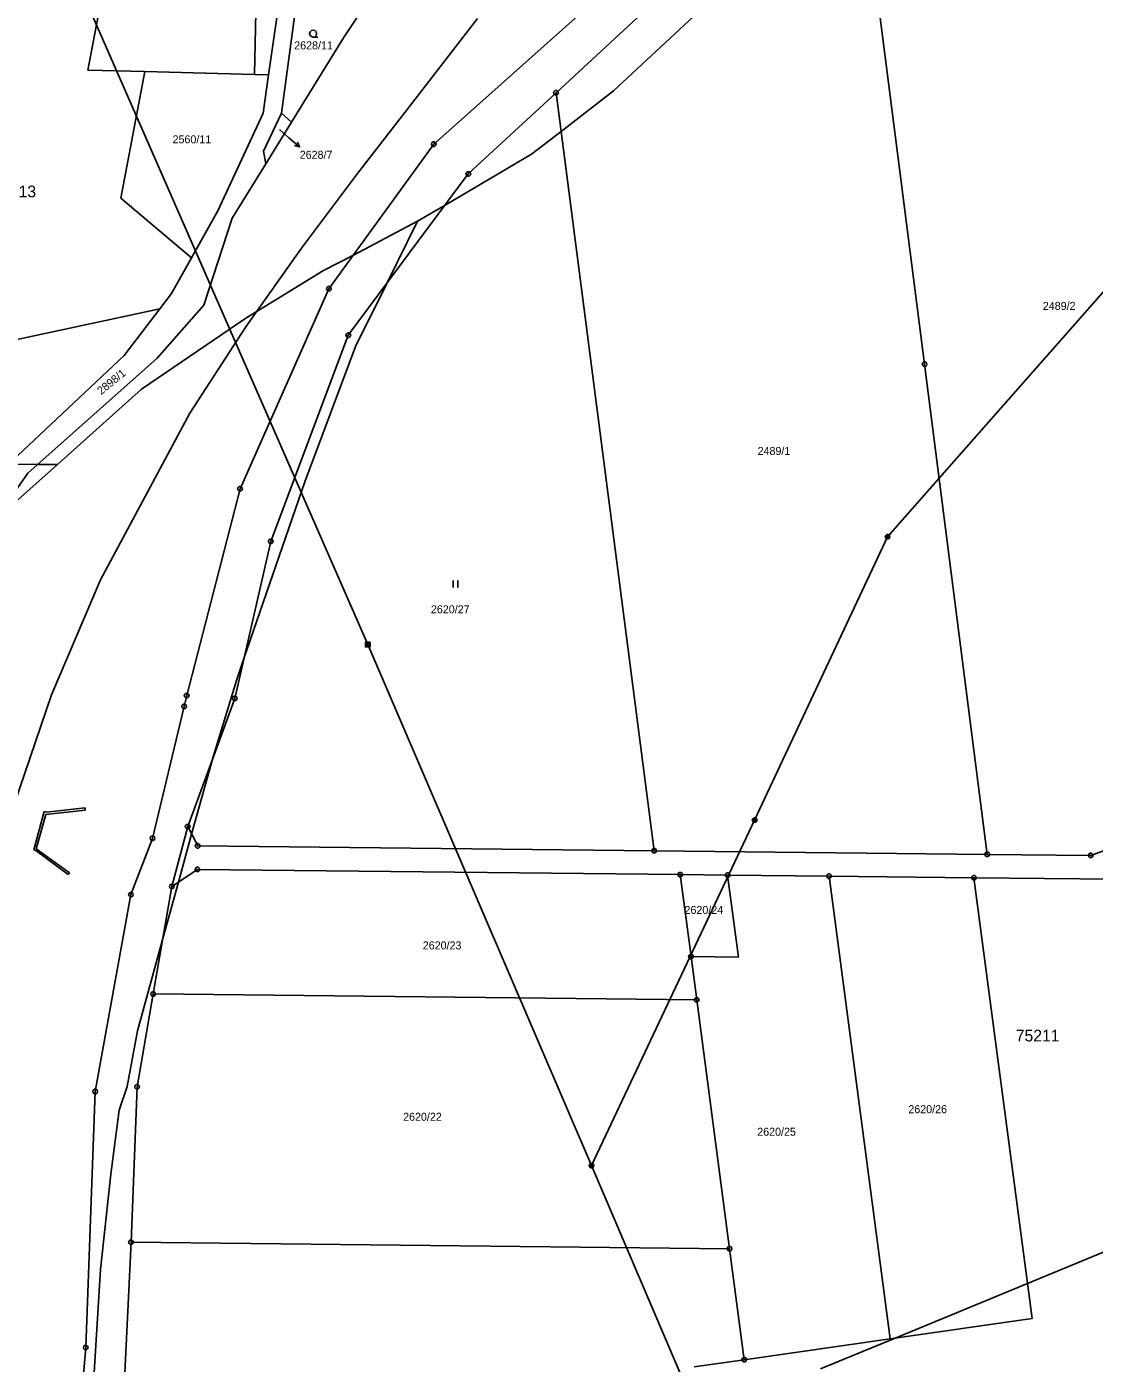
# Model space of a CAD drawing. Extents: x -760611 to -758411, y -1176479 to -1174807.
# Drawn here: x -759476.2 to -759249.4, y -1175576.9 to -1175293 of the extents above; entities that cross this region are included whole.
import ezdxf

# ---------------------------------------------------------------- set-up
doc = ezdxf.new("R2010")
doc.units = 0
for name, color, linetype in [('1', 7, 'Continuous'), ('11', 7, 'Continuous'), ('2', 7, 'Continuous'), ('3', 7, 'Continuous'), ('4', 7, 'Continuous'), ('6', 7, 'Continuous'), ('7', 7, 'Continuous'), ('8', 7, 'Continuous')]:
    doc.layers.add(name, color=color, linetype=linetype)

msp = doc.modelspace()

# ---------------------------------------------------------------- linework, layer by layer
at = {"layer": '1'}
for p, q in [((-759298.74, -1175260.61), (-759285.43, -1175364.72)), ((-759463.25, -1175302.25), (-759458.35, -1175276.62)), ((-759347.43, -1175280.29), (-759389.73, -1175317.99)), ((-759422.12, -1175311.42), (-759418.19, -1175282.22)), ((-759427.83, -1175303.15), (-759427.43, -1175284.24)), ((-759339.76, -1175284.87), (-759363.75, -1175307.07)), ((-759424.83, -1175303.24), (-759422.71, -1175288.64)), ((-759403.18, -1175286.77), (-759408.89, -1175295.4)), ((-759419.93, -1175313.27), (-759408.89, -1175295.4)), ((-759451.11, -1175302.56), (-759463.25, -1175302.25)), ((-759451.11, -1175302.56), (-759456.26, -1175329.44)), ((-759427.83, -1175303.15), (-759451.11, -1175302.56)), ((-759427.83, -1175303.15), (-759424.83, -1175303.24)), ((-759426, -1175311.4), (-759424.83, -1175303.24)), ((-759363.75, -1175307.07), (-759382.39, -1175324.31)), ((-759363.75, -1175307.07), (-759342.89, -1175468.06)), ((-759435.63, -1175332.11), (-759426, -1175311.4)), ((-759422.12, -1175311.42), (-759425.89, -1175319.48)), ((-759419.93, -1175313.27), (-759422.12, -1175311.42)), ((-759419.93, -1175313.27), (-759425.41, -1175322.14)), ((-759425.89, -1175319.48), (-759425.41, -1175322.14)), ((-759389.73, -1175317.99), (-759412.01, -1175348.67)), ((-759432.55, -1175333.69), (-759425.41, -1175322.14)), ((-759382.39, -1175324.31), (-759407.89, -1175358.56)), ((-759456.26, -1175329.44), (-759441.23, -1175342.14)), ((-759441.23, -1175342.14), (-759435.63, -1175332.11)), ((-759438.6, -1175352.18), (-759432.55, -1175333.69)), ((-759445.44, -1175349.68), (-759441.23, -1175342.14)), ((-759412.01, -1175348.67), (-759430.9, -1175391.19)), ((-759447.94, -1175352.94), (-759445.44, -1175349.68)), ((-759447.94, -1175352.94), (-759567.99, -1175378.71)), ((-759455.51, -1175362.85), (-759447.94, -1175352.94)), ((-759448.52, -1175363.4), (-759438.6, -1175352.18)), ((-759407.89, -1175358.56), (-759424.37, -1175402.34)), ((-759479.36, -1175385.29), (-759455.51, -1175362.85)), ((-759475.96, -1175387.88), (-759448.52, -1175363.4)), ((-759272.12, -1175468.82), (-759285.43, -1175364.72)), ((-759482.98, -1175397.79), (-759475.96, -1175387.88)), ((-759430.9, -1175391.19), (-759442.24, -1175435.11)), ((-759424.37, -1175402.34), (-759432, -1175435.71)), ((-759442.24, -1175435.11), (-759442.77, -1175437.4)), ((-759432, -1175435.71), (-759442.02, -1175462.93)), ((-759442.77, -1175437.4), (-759449.49, -1175465.42)), ((-759449.49, -1175465.42), (-759454.08, -1175477.37)), ((-759442.02, -1175462.93), (-759445.38, -1175475.63)), ((-759439.9, -1175467.02), (-759442.02, -1175462.93)), ((-759439.9, -1175467.02), (-759342.89, -1175468.06)), ((-759342.89, -1175468.06), (-759272.12, -1175468.82)), ((-759243.97, -1175466.82), (-759250.12, -1175469.05)), ((-759272.12, -1175468.82), (-759250.12, -1175469.05)), ((-759439.95, -1175472.02), (-759445.38, -1175475.63)), ((-759337.38, -1175473.12), (-759439.95, -1175472.02)), ((-759335.07, -1175490.55), (-759337.38, -1175473.12)), ((-759337.38, -1175473.12), (-759327.28, -1175473.23)), ((-759327.28, -1175473.23), (-759324.97, -1175490.65)), ((-759305.73, -1175473.46), (-759327.28, -1175473.23)), ((-759305.73, -1175473.46), (-759292.73, -1175571.71)), ((-759274.94, -1175473.79), (-759305.73, -1175473.46)), ((-759274.94, -1175473.79), (-759244.94, -1175474.11)), ((-759262.56, -1175567.39), (-759274.94, -1175473.79)), ((-759445.38, -1175475.63), (-759449.35, -1175498.48)), ((-759454.08, -1175477.37), (-759461.69, -1175519.2)), ((-759333.86, -1175499.72), (-759335.07, -1175490.55)), ((-759324.97, -1175490.65), (-759335.07, -1175490.55)), ((-759449.35, -1175498.48), (-759452.78, -1175518.19)), ((-759449.35, -1175498.48), (-759333.86, -1175499.72)), ((-759326.87, -1175552.58), (-759333.86, -1175499.72)), ((-759461.69, -1175519.2), (-759463.68, -1175573.58)), ((-759452.78, -1175518.19), (-759454.06, -1175551.22)), ((-759457.17, -1175615.9), (-759454.06, -1175551.22)), ((-759326.87, -1175552.58), (-759454.06, -1175551.22)), ((-759323.75, -1175576.16), (-759326.87, -1175552.58)), ((-759292.73, -1175571.71), (-759262.56, -1175567.39)), ((-759323.75, -1175576.16), (-759292.73, -1175571.71)), ((-759463.68, -1175573.58), (-759467.05, -1175613.8)), ((-759334.43, -1175577.69), (-759323.75, -1175576.16))]:
    msp.add_line(p, q, dxfattribs=at)
at = {"layer": '11'}
for points in [[(-759393.16, -1175334.36), (-759387.3, -1175330.9), (-759368.94, -1175320.09), (-759362.69, -1175315.26), (-759351.51, -1175306.64), (-759322.58, -1175279.7), (-759303.02, -1175265.41), (-759302.17, -1175262.03)], [(-759469.67, -1175386.02), (-759451.81, -1175370.03), (-759429.7, -1175354.91), (-759413.13, -1175344.84), (-759406.82, -1175341.53), (-759393.16, -1175334.36)], [(-759393.16, -1175334.36), (-759399.81, -1175347.71), (-759406.4, -1175360.95), (-759417.11, -1175389.67)], [(-759479.79, -1175385.97), (-759473.85, -1175386), (-759469.67, -1175386.02)], [(-759478.18, -1175393.6), (-759469.67, -1175386.02)], [(-759417.11, -1175389.67), (-759430.06, -1175427.22), (-759431.68, -1175431.91), (-759436.83, -1175448.81), (-759436.84, -1175448.85), (-759441.18, -1175464.55), (-759443.99, -1175474.7), (-759447.3, -1175486.67), (-759452.72, -1175506.28), (-759454.89, -1175518.12), (-759456.6, -1175523.19), (-759458.34, -1175536.72), (-759460.54, -1175557.02), (-759462.34, -1175585.79), (-759461.62, -1175621.33), (-759460.4, -1175636.57), (-759460.44, -1175646.73), (-759456.01, -1175714.03)], [(-759307.54, -1175578.1), (-759291.72, -1175571.57), (-759263.55, -1175559.94), (-759222.29, -1175542.91)]]:
    msp.add_lwpolyline(points, dxfattribs=at)
at = {"layer": '3'}
for p, q in [((-759385.64, -1175410.66), (-759385.64, -1175412.16)), ((-759384.64, -1175412.16), (-759384.64, -1175410.66))]:
    msp.add_line(p, q, dxfattribs=at)
msp.add_lwpolyline([(-759415.36, -1175295.24), (-759415.74, -1175295.14), (-759416.01, -1175294.87), (-759416.11, -1175294.5), (-759416.01, -1175294.13), (-759415.74, -1175293.86), (-759415.37, -1175293.76), (-759415, -1175293.86), (-759414.73, -1175294.13), (-759414.63, -1175294.51), (-759414.73, -1175294.89), (-759415, -1175295.16), (-759415.38, -1175295.26), (-759414.38, -1175295.26)], dxfattribs=at)
at = {"layer": '4'}
for p, q in [((-759474.71, -1175467.87), (-759472.51, -1175459.72)), ((-759472.51, -1175459.72), (-759472.03, -1175459.85)), ((-759463.78, -1175459.43), (-759472.17, -1175460.33)), ((-759472.03, -1175459.85), (-759463.83, -1175458.93)), ((-759463.83, -1175458.93), (-759463.78, -1175459.43)), ((-759472.17, -1175460.33), (-759474.19, -1175467.62)), ((-759474.3, -1175468), (-759474.71, -1175467.87)), ((-759467.44, -1175473.12), (-759474.3, -1175468)), ((-759474.19, -1175467.62), (-759467.15, -1175472.72)), ((-759467.15, -1175472.72), (-759467.44, -1175473.12))]:
    msp.add_line(p, q, dxfattribs=at)
at = {"layer": '6'}
for p, q in [((-759403.75, -1175424.27), (-759478.28, -1175254.17)), ((-759380.41, -1175291.31), (-759393.68, -1175308.39)), ((-759393.68, -1175308.39), (-759405.91, -1175324.2)), ((-759220.08, -1175318.2), (-759293.3, -1175401.37)), ((-759405.91, -1175324.2), (-759417.82, -1175340.04)), ((-759417.82, -1175340.04), (-759429.67, -1175356.76)), ((-759429.67, -1175356.76), (-759441.55, -1175375.13)), ((-759441.55, -1175375.13), (-759460.56, -1175410.52)), ((-759293.3, -1175401.37), (-759321.55, -1175461.54)), ((-759460.56, -1175410.52), (-759470.94, -1175434.97)), ((-759356.23, -1175534.93), (-759403.75, -1175424.27)), ((-759470.94, -1175434.97), (-759478.91, -1175458.25)), ((-759321.55, -1175461.54), (-759356.23, -1175534.93)), ((-759356.23, -1175534.93), (-759318.62, -1175622.68))]:
    msp.add_line(p, q, dxfattribs=at)
for points in [[(-759293.45, -1175400.89), (-759293.14, -1175400.89), (-759292.89, -1175401.07), (-759292.79, -1175401.36), (-759292.89, -1175401.65), (-759293.14, -1175401.83), (-759293.45, -1175401.83), (-759293.7, -1175401.65), (-759293.8, -1175401.36), (-759293.7, -1175401.07), (-759293.45, -1175400.89), (-759293.42, -1175400.93), (-759293.18, -1175400.93), (-759293.02, -1175401.01), (-759293.58, -1175401.01), (-759293.66, -1175401.09), (-759292.94, -1175401.09), (-759292.94, -1175401.17), (-759293.66, -1175401.17), (-759293.7, -1175401.25), (-759292.9, -1175401.25), (-759292.86, -1175401.33), (-759293.74, -1175401.33), (-759293.74, -1175401.41), (-759292.86, -1175401.41), (-759292.89, -1175401.49), (-759293.7, -1175401.49), (-759293.69, -1175401.57), (-759292.88, -1175401.57), (-759292.93, -1175401.65), (-759293.65, -1175401.65), (-759293.57, -1175401.73), (-759293.01, -1175401.73), (-759293.12, -1175401.81), (-759293.46, -1175401.81)], [(-759404.25, -1175423.77), (-759403.25, -1175423.77), (-759403.25, -1175424.77), (-759404.25, -1175424.77), (-759404.25, -1175423.77), (-759404.19, -1175423.83), (-759403.31, -1175423.83), (-759403.31, -1175423.91), (-759404.19, -1175423.91), (-759404.19, -1175423.99), (-759403.31, -1175423.99), (-759403.31, -1175424.07), (-759404.19, -1175424.07), (-759404.19, -1175424.15), (-759403.31, -1175424.15), (-759403.31, -1175424.23), (-759404.19, -1175424.23), (-759404.19, -1175424.31), (-759403.31, -1175424.31), (-759403.31, -1175424.39), (-759404.19, -1175424.39), (-759404.19, -1175424.47), (-759403.31, -1175424.47), (-759403.31, -1175424.55), (-759404.19, -1175424.55), (-759404.19, -1175424.63), (-759403.31, -1175424.63), (-759403.31, -1175424.71), (-759404.19, -1175424.71)], [(-759321.7, -1175461.06), (-759321.39, -1175461.06), (-759321.14, -1175461.24), (-759321.04, -1175461.53), (-759321.14, -1175461.82), (-759321.39, -1175462), (-759321.7, -1175462), (-759321.95, -1175461.82), (-759322.05, -1175461.53), (-759321.95, -1175461.24), (-759321.7, -1175461.06), (-759321.67, -1175461.1), (-759321.43, -1175461.1), (-759321.27, -1175461.18), (-759321.83, -1175461.18), (-759321.91, -1175461.26), (-759321.19, -1175461.26), (-759321.19, -1175461.34), (-759321.91, -1175461.34), (-759321.95, -1175461.42), (-759321.15, -1175461.42), (-759321.11, -1175461.5), (-759321.99, -1175461.5), (-759321.99, -1175461.58), (-759321.11, -1175461.58), (-759321.14, -1175461.66), (-759321.95, -1175461.66), (-759321.94, -1175461.74), (-759321.13, -1175461.74), (-759321.18, -1175461.82), (-759321.9, -1175461.82), (-759321.82, -1175461.9), (-759321.26, -1175461.9), (-759321.37, -1175461.98), (-759321.71, -1175461.98)], [(-759356.38, -1175534.45), (-759356.07, -1175534.45), (-759355.82, -1175534.63), (-759355.72, -1175534.92), (-759355.82, -1175535.21), (-759356.07, -1175535.39), (-759356.38, -1175535.39), (-759356.63, -1175535.21), (-759356.73, -1175534.92), (-759356.63, -1175534.63), (-759356.38, -1175534.45), (-759356.35, -1175534.49), (-759356.11, -1175534.49), (-759355.95, -1175534.57), (-759356.51, -1175534.57), (-759356.59, -1175534.65), (-759355.87, -1175534.65), (-759355.87, -1175534.73), (-759356.59, -1175534.73), (-759356.63, -1175534.81), (-759355.83, -1175534.81), (-759355.79, -1175534.89), (-759356.67, -1175534.89), (-759356.67, -1175534.97), (-759355.79, -1175534.97), (-759355.82, -1175535.05), (-759356.63, -1175535.05), (-759356.62, -1175535.13), (-759355.81, -1175535.13), (-759355.86, -1175535.21), (-759356.58, -1175535.21), (-759356.5, -1175535.29), (-759355.94, -1175535.29), (-759356.05, -1175535.37), (-759356.39, -1175535.37)]]:
    msp.add_lwpolyline(points, dxfattribs=at)
at = {"layer": '7'}
for p in [(-759422.44, -1175314.95), (-759418.26, -1175318.56)]:
    msp.add_line(p, (-759420.53, -1175316.6), dxfattribs=at)
msp.add_lwpolyline([(-759418.69, -1175317.53), (-759418.26, -1175318.56), (-759419.34, -1175318.29)], dxfattribs=at)
at = {"layer": '8'}
for p, q in [((-759363.87, -1175307.07), (-759363.63, -1175307.07)), ((-759389.85, -1175317.99), (-759389.61, -1175317.99)), ((-759382.51, -1175324.31), (-759382.27, -1175324.31)), ((-759412.13, -1175348.67), (-759411.89, -1175348.67)), ((-759408.01, -1175358.56), (-759407.77, -1175358.56)), ((-759285.55, -1175364.72), (-759285.31, -1175364.72)), ((-759431.02, -1175391.19), (-759430.78, -1175391.19)), ((-759424.49, -1175402.34), (-759424.25, -1175402.34)), ((-759442.36, -1175435.11), (-759442.12, -1175435.11)), ((-759432.12, -1175435.71), (-759431.88, -1175435.71)), ((-759442.89, -1175437.4), (-759442.65, -1175437.4)), ((-759449.61, -1175465.42), (-759449.37, -1175465.42)), ((-759442.14, -1175462.93), (-759441.9, -1175462.93)), ((-759440.02, -1175467.02), (-759439.78, -1175467.02)), ((-759343.01, -1175468.06), (-759342.77, -1175468.06)), ((-759272.24, -1175468.82), (-759272, -1175468.82)), ((-759250.24, -1175469.05), (-759250, -1175469.05)), ((-759440.07, -1175472.02), (-759439.83, -1175472.02)), ((-759337.5, -1175473.12), (-759337.26, -1175473.12)), ((-759327.4, -1175473.23), (-759327.16, -1175473.23)), ((-759305.85, -1175473.46), (-759305.61, -1175473.46)), ((-759275.06, -1175473.79), (-759274.82, -1175473.79)), ((-759445.5, -1175475.63), (-759445.26, -1175475.63)), ((-759454.2, -1175477.37), (-759453.96, -1175477.37)), ((-759335.19, -1175490.55), (-759334.95, -1175490.55)), ((-759449.47, -1175498.48), (-759449.23, -1175498.48)), ((-759333.98, -1175499.72), (-759333.74, -1175499.72)), ((-759461.81, -1175519.2), (-759461.57, -1175519.2)), ((-759452.9, -1175518.19), (-759452.66, -1175518.19)), ((-759454.18, -1175551.22), (-759453.94, -1175551.22)), ((-759326.99, -1175552.58), (-759326.75, -1175552.58)), ((-759463.8, -1175573.58), (-759463.56, -1175573.58)), ((-759323.87, -1175576.16), (-759323.63, -1175576.16))]:
    msp.add_line(p, q, dxfattribs=at)
for points in [[(-759363.6, -1175306.59), (-759363.35, -1175306.77), (-759363.25, -1175307.06), (-759363.35, -1175307.35), (-759363.6, -1175307.53), (-759363.91, -1175307.53), (-759364.16, -1175307.35), (-759364.26, -1175307.06), (-759364.16, -1175306.77), (-759363.91, -1175306.59)], [(-759389.58, -1175317.51), (-759389.33, -1175317.69), (-759389.23, -1175317.98), (-759389.33, -1175318.27), (-759389.58, -1175318.45), (-759389.89, -1175318.45), (-759390.14, -1175318.27), (-759390.24, -1175317.98), (-759390.14, -1175317.69), (-759389.89, -1175317.51)], [(-759382.24, -1175323.83), (-759381.99, -1175324.01), (-759381.89, -1175324.3), (-759381.99, -1175324.59), (-759382.24, -1175324.77), (-759382.55, -1175324.77), (-759382.8, -1175324.59), (-759382.9, -1175324.3), (-759382.8, -1175324.01), (-759382.55, -1175323.83)], [(-759411.86, -1175348.19), (-759411.61, -1175348.37), (-759411.51, -1175348.66), (-759411.61, -1175348.95), (-759411.86, -1175349.13), (-759412.17, -1175349.13), (-759412.42, -1175348.95), (-759412.52, -1175348.66), (-759412.42, -1175348.37), (-759412.17, -1175348.19)], [(-759407.74, -1175358.08), (-759407.49, -1175358.26), (-759407.39, -1175358.55), (-759407.49, -1175358.84), (-759407.74, -1175359.02), (-759408.05, -1175359.02), (-759408.3, -1175358.84), (-759408.4, -1175358.55), (-759408.3, -1175358.26), (-759408.05, -1175358.08)], [(-759285.28, -1175364.24), (-759285.03, -1175364.42), (-759284.93, -1175364.71), (-759285.03, -1175365), (-759285.28, -1175365.18), (-759285.59, -1175365.18), (-759285.84, -1175365), (-759285.94, -1175364.71), (-759285.84, -1175364.42), (-759285.59, -1175364.24)], [(-759430.75, -1175390.71), (-759430.5, -1175390.89), (-759430.4, -1175391.18), (-759430.5, -1175391.47), (-759430.75, -1175391.65), (-759431.06, -1175391.65), (-759431.31, -1175391.47), (-759431.41, -1175391.18), (-759431.31, -1175390.89), (-759431.06, -1175390.71)], [(-759424.22, -1175401.86), (-759423.97, -1175402.04), (-759423.87, -1175402.33), (-759423.97, -1175402.62), (-759424.22, -1175402.8), (-759424.53, -1175402.8), (-759424.78, -1175402.62), (-759424.88, -1175402.33), (-759424.78, -1175402.04), (-759424.53, -1175401.86)], [(-759442.62, -1175436.92), (-759442.37, -1175437.1), (-759442.27, -1175437.39), (-759442.37, -1175437.68), (-759442.62, -1175437.86), (-759442.93, -1175437.86), (-759443.18, -1175437.68), (-759443.28, -1175437.39), (-759443.18, -1175437.1), (-759442.93, -1175436.92)], [(-759442.09, -1175434.63), (-759441.84, -1175434.81), (-759441.74, -1175435.1), (-759441.84, -1175435.39), (-759442.09, -1175435.57), (-759442.4, -1175435.57), (-759442.65, -1175435.39), (-759442.75, -1175435.1), (-759442.65, -1175434.81), (-759442.4, -1175434.63)], [(-759431.85, -1175435.23), (-759431.6, -1175435.41), (-759431.5, -1175435.7), (-759431.6, -1175435.99), (-759431.85, -1175436.17), (-759432.16, -1175436.17), (-759432.41, -1175435.99), (-759432.51, -1175435.7), (-759432.41, -1175435.41), (-759432.16, -1175435.23)], [(-759441.87, -1175462.45), (-759441.62, -1175462.63), (-759441.52, -1175462.92), (-759441.62, -1175463.21), (-759441.87, -1175463.39), (-759442.18, -1175463.39), (-759442.43, -1175463.21), (-759442.53, -1175462.92), (-759442.43, -1175462.63), (-759442.18, -1175462.45)], [(-759449.34, -1175464.94), (-759449.09, -1175465.12), (-759448.99, -1175465.41), (-759449.09, -1175465.7), (-759449.34, -1175465.88), (-759449.65, -1175465.88), (-759449.9, -1175465.7), (-759450, -1175465.41), (-759449.9, -1175465.12), (-759449.65, -1175464.94)], [(-759439.75, -1175466.54), (-759439.5, -1175466.72), (-759439.4, -1175467.01), (-759439.5, -1175467.3), (-759439.75, -1175467.48), (-759440.06, -1175467.48), (-759440.31, -1175467.3), (-759440.41, -1175467.01), (-759440.31, -1175466.72), (-759440.06, -1175466.54)], [(-759342.74, -1175467.58), (-759342.49, -1175467.76), (-759342.39, -1175468.05), (-759342.49, -1175468.34), (-759342.74, -1175468.52), (-759343.05, -1175468.52), (-759343.3, -1175468.34), (-759343.4, -1175468.05), (-759343.3, -1175467.76), (-759343.05, -1175467.58)], [(-759271.97, -1175468.34), (-759271.72, -1175468.52), (-759271.62, -1175468.81), (-759271.72, -1175469.1), (-759271.97, -1175469.28), (-759272.28, -1175469.28), (-759272.53, -1175469.1), (-759272.63, -1175468.81), (-759272.53, -1175468.52), (-759272.28, -1175468.34)], [(-759249.97, -1175468.57), (-759249.72, -1175468.75), (-759249.62, -1175469.04), (-759249.72, -1175469.33), (-759249.97, -1175469.51), (-759250.28, -1175469.51), (-759250.53, -1175469.33), (-759250.63, -1175469.04), (-759250.53, -1175468.75), (-759250.28, -1175468.57)], [(-759439.8, -1175471.54), (-759439.55, -1175471.72), (-759439.45, -1175472.01), (-759439.55, -1175472.3), (-759439.8, -1175472.48), (-759440.11, -1175472.48), (-759440.36, -1175472.3), (-759440.46, -1175472.01), (-759440.36, -1175471.72), (-759440.11, -1175471.54)], [(-759337.23, -1175472.64), (-759336.98, -1175472.82), (-759336.88, -1175473.11), (-759336.98, -1175473.4), (-759337.23, -1175473.58), (-759337.54, -1175473.58), (-759337.79, -1175473.4), (-759337.89, -1175473.11), (-759337.79, -1175472.82), (-759337.54, -1175472.64)], [(-759327.13, -1175472.75), (-759326.88, -1175472.93), (-759326.78, -1175473.22), (-759326.88, -1175473.51), (-759327.13, -1175473.69), (-759327.44, -1175473.69), (-759327.69, -1175473.51), (-759327.79, -1175473.22), (-759327.69, -1175472.93), (-759327.44, -1175472.75)], [(-759305.58, -1175472.98), (-759305.33, -1175473.16), (-759305.23, -1175473.45), (-759305.33, -1175473.74), (-759305.58, -1175473.92), (-759305.89, -1175473.92), (-759306.14, -1175473.74), (-759306.24, -1175473.45), (-759306.14, -1175473.16), (-759305.89, -1175472.98)], [(-759274.79, -1175473.31), (-759274.54, -1175473.49), (-759274.44, -1175473.78), (-759274.54, -1175474.07), (-759274.79, -1175474.25), (-759275.1, -1175474.25), (-759275.35, -1175474.07), (-759275.45, -1175473.78), (-759275.35, -1175473.49), (-759275.1, -1175473.31)], [(-759453.93, -1175476.89), (-759453.68, -1175477.07), (-759453.58, -1175477.36), (-759453.68, -1175477.65), (-759453.93, -1175477.83), (-759454.24, -1175477.83), (-759454.49, -1175477.65), (-759454.59, -1175477.36), (-759454.49, -1175477.07), (-759454.24, -1175476.89)], [(-759445.23, -1175475.15), (-759444.98, -1175475.33), (-759444.88, -1175475.62), (-759444.98, -1175475.91), (-759445.23, -1175476.09), (-759445.54, -1175476.09), (-759445.79, -1175475.91), (-759445.89, -1175475.62), (-759445.79, -1175475.33), (-759445.54, -1175475.15)], [(-759334.92, -1175490.07), (-759334.67, -1175490.25), (-759334.57, -1175490.54), (-759334.67, -1175490.83), (-759334.92, -1175491.01), (-759335.23, -1175491.01), (-759335.48, -1175490.83), (-759335.58, -1175490.54), (-759335.48, -1175490.25), (-759335.23, -1175490.07)], [(-759449.2, -1175498), (-759448.95, -1175498.18), (-759448.85, -1175498.47), (-759448.95, -1175498.76), (-759449.2, -1175498.94), (-759449.51, -1175498.94), (-759449.76, -1175498.76), (-759449.86, -1175498.47), (-759449.76, -1175498.18), (-759449.51, -1175498)], [(-759333.71, -1175499.24), (-759333.46, -1175499.42), (-759333.36, -1175499.71), (-759333.46, -1175500), (-759333.71, -1175500.18), (-759334.02, -1175500.18), (-759334.27, -1175500), (-759334.37, -1175499.71), (-759334.27, -1175499.42), (-759334.02, -1175499.24)], [(-759461.54, -1175518.72), (-759461.29, -1175518.9), (-759461.19, -1175519.19), (-759461.29, -1175519.48), (-759461.54, -1175519.66), (-759461.85, -1175519.66), (-759462.1, -1175519.48), (-759462.2, -1175519.19), (-759462.1, -1175518.9), (-759461.85, -1175518.72)], [(-759452.63, -1175517.71), (-759452.38, -1175517.89), (-759452.28, -1175518.18), (-759452.38, -1175518.47), (-759452.63, -1175518.65), (-759452.94, -1175518.65), (-759453.19, -1175518.47), (-759453.29, -1175518.18), (-759453.19, -1175517.89), (-759452.94, -1175517.71)], [(-759453.91, -1175550.74), (-759453.66, -1175550.92), (-759453.56, -1175551.21), (-759453.66, -1175551.5), (-759453.91, -1175551.68), (-759454.22, -1175551.68), (-759454.47, -1175551.5), (-759454.57, -1175551.21), (-759454.47, -1175550.92), (-759454.22, -1175550.74)], [(-759326.72, -1175552.1), (-759326.47, -1175552.28), (-759326.37, -1175552.57), (-759326.47, -1175552.86), (-759326.72, -1175553.04), (-759327.03, -1175553.04), (-759327.28, -1175552.86), (-759327.38, -1175552.57), (-759327.28, -1175552.28), (-759327.03, -1175552.1)], [(-759463.53, -1175573.1), (-759463.28, -1175573.28), (-759463.18, -1175573.57), (-759463.28, -1175573.86), (-759463.53, -1175574.04), (-759463.84, -1175574.04), (-759464.09, -1175573.86), (-759464.19, -1175573.57), (-759464.09, -1175573.28), (-759463.84, -1175573.1)], [(-759323.6, -1175575.68), (-759323.35, -1175575.86), (-759323.25, -1175576.15), (-759323.35, -1175576.44), (-759323.6, -1175576.62), (-759323.91, -1175576.62), (-759324.16, -1175576.44), (-759324.26, -1175576.15), (-759324.16, -1175575.86), (-759323.91, -1175575.68)]]:
    msp.add_lwpolyline(points, close=True, dxfattribs=at)

# ---------------------------------------------------------------- texts
at = {"layer": '11'}
for s, p in [('75313', (-759483.54, -1175329.27)), ('75211', (-759266.06, -1175508.56))]:
    msp.add_text(s, height=2.5, dxfattribs=at).set_placement(p)
at = {"layer": '2'}
for s, height, p in [('2628/11', 1.7, (-759419.39, -1175297.84)), ('2628/7', 0.1, (-759422.69, -1175314.95)), ('2560/11', 1.7, (-759445.24, -1175317.8)), ('2489/2', 1.7, (-759260.31, -1175353.18)), ('2489/1', 1.7, (-759320.92, -1175383.99)), ('2620/27', 1.7, (-759390.34, -1175417.62)), ('2620/24', 1.7, (-759336.45, -1175481.48)), ('2620/23', 1.7, (-759392.07, -1175489.01)), ('2620/26', 1.7, (-759288.89, -1175523.8)), ('2620/22', 1.7, (-759396.25, -1175525.41)), ('2620/25', 1.7, (-759321, -1175528.59))]:
    msp.add_text(s, height=height, dxfattribs=at).set_placement(p)
msp.add_text('2898/1', height=1.7, rotation=38.9611, dxfattribs=at).set_placement((-759460.41, -1175371.29))
at = {"layer": '7'}
msp.add_text('2628/7', height=1.7, dxfattribs=at).set_placement((-759418.22, -1175321.08))

doc.saveas('drawing.dxf')
